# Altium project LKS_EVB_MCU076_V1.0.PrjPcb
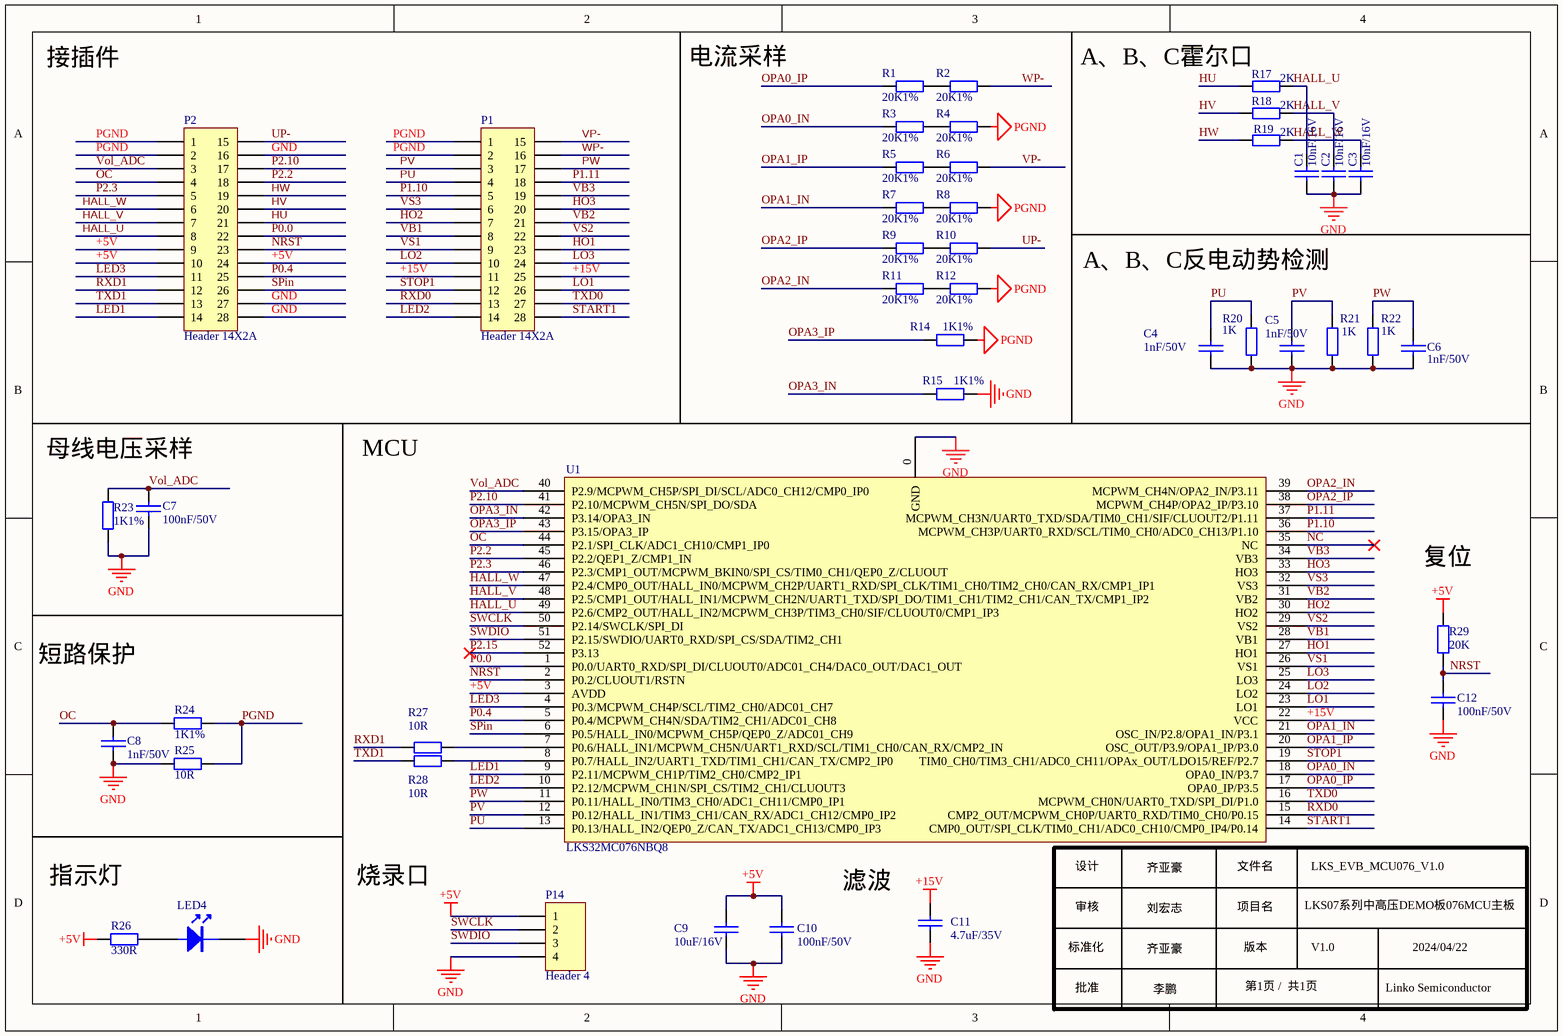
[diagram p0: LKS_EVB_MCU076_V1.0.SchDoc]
1 sheet, 44 parts. Net scope: global (net labels, ports and power ports of the same name join across sheets).
Board file: LKS_EVB_MCU076_V1.0.PcbDoc

## Sheet LKS_EVB_MCU076_V1.0.SchDoc
size A4; SheetNumber: 1; SheetTotal: 1

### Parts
C1  10nF/16V  [0603C]
C2  10nF/16V  [0603C]
C3  10nF/16V  [0603C]
C4  1nF/50V  [0603C]
C5  1nF/50V  [0603C]
C6  1nF/50V  [0603C]
C7  100nF/50V  [0603C]
C8  1nF/50V  [0603C]
C9  10uF/16V  [0603C]
C10  100nF/50V  [0603C]
C11  4.7uF/35V  [0603C]
C12  100nF/50V  [0603C]
LED4  LED  [LED 0603R]  (value not drawn)
P1  Header 14X2A  [HDR 2X14 底层]
P2  Header 14X2A  [HDR 2X14 底层]
P14  Header 4  [HDR 1X4]
R1  20K1%  [0603R]
R2  20K1%  [0603R]
R3  20K1%  [0603R]
R4  20K1%  [0603R]
R5  20K1%  [0603R]
R6  20K1%  [0603R]
R7  20K1%  [0603R]
R8  20K1%  [0603R]
R9  20K1%  [0603R]
R10  20K1%  [0603R]
R11  20K1%  [0603R]
R12  20K1%  [0603R]
R14  1K1%  [0603R]
R15  1K1%  [0603R]
R17  2K  [0603R]
R18  2K  [0603R]
R19  2K  [0603R]
R20  1K  [0603R]
R21  1K  [0603R]
R22  1K  [0603R]
R23  1K1%  [0603R]
R24  1K1%  [0603R]
R25  10R  [0603R]
R26  330R  [0603R]
R27  10R  [0603R]
R28  10R  [0603R]
R29  20K  [0603R]
U1  LKS32MC076NBQ8  [QFN52]

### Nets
+5V: C9.2 C10.2 P2.9 P2.10 P2.24 P14.1 R26.1 R29.1 U1.3(AVDD)
+15V: C11.2 P1.11 P1.25 U1.22(VCC)
GND: C1.2 C2.2 C3.2 C4.2 C5.2 C6.2 C7.1 C8.1 C9.1 C10.1 C11.1 C12.2 LED4.2(K) P2.16 P2.27 P2.28 P14.4 R15.1 R20.2 R21.2 R22.2 R23.1 R25.2 U1.0(GND)
PGND: P1.1 P1.2 P2.1 P2.2 R4.1 R8.1 R12.1 R14.1 R24.2 R25.1
HALL_U: C1.1 P2.8 R17.2 U1.49(P2.6/CMP2_OUT/HALL_IN2/MCPWM_CH3P/TIM3_CH0/SIF/CLUOUT0/CMP1_IP3)
HALL_V: C2.1 P2.7 R18.2 U1.48(P2.5/CMP1_OUT/HALL_IN1/MCPWM_CH2N/UART1_TXD/SPI_DO/TIM1_CH1/TIM2_CH1/CAN_TX/CMP1_IP2)
HALL_W: C3.1 P2.6 R19.2 U1.47(P2.4/CMP0_OUT/HALL_IN0/MCPWM_CH2P/UART1_RXD/SPI_CLK/TIM1_CH0/TIM2_CH0/CAN_RX/CMP1_IP1)
HO1: P1.23 U1.27(HO1)
HO2: P1.7 U1.30(HO2)
HO3: P1.20 U1.33(HO3)
HU: P2.21 R17.1
HV: P2.20 R18.1
HW: P2.19 R19.1
LED1: P2.14 U1.9(P2.11/MCPWM_CH1P/TIM2_CH0/CMP2_IP1)
LED2: P1.14 U1.10(P2.12/MCPWM_CH1N/SPI_CS/TIM2_CH1/CLUOUT3)
LED3: P2.11 U1.4(P0.3/MCPWM_CH4P/SCL/TIM2_CH0/ADC01_CH7)
LO1: P1.26 U1.23(LO1)
LO2: P1.10 U1.24(LO2)
LO3: P1.24 U1.25(LO3)
NC: U1.35(NC)
NRST: C12.1 P2.23 R29.2 U1.2(P0.2/CLUOUT1/RSTN)
OC: C8.2 P2.4 R24.1 U1.44(P2.1/SPI_CLK/ADC1_CH10/CMP1_IP0)
OPA0_IN: R3.2 U1.18(OPA0_IN/P3.7)
OPA0_IP: R1.2 U1.17(OPA0_IP/P3.5)
OPA1_IN: R7.2 U1.21(OSC_IN/P2.8/OPA1_IN/P3.1)
OPA1_IP: R5.2 U1.20(OSC_OUT/P3.9/OPA1_IP/P3.0)
OPA2_IN: R11.2 U1.39(MCPWM_CH4N/OPA2_IN/P3.11)
OPA2_IP: R9.2 U1.38(MCPWM_CH4P/OPA2_IP/P3.10)
OPA3_IN: R15.2 U1.42(P3.14/OPA3_IN)
OPA3_IP: R14.2 U1.43(P3.15/OPA3_IP)
P0.0: P2.22 U1.1(P0.0/UART0_RXD/SPI_DI/CLUOUT0/ADC01_CH4/DAC0_OUT/DAC1_OUT)
P0.4: P2.25 U1.5(P0.4/MCPWM_CH4N/SDA/TIM2_CH1/ADC01_CH8)
P1.10: P1.5 U1.36(MCPWM_CH3P/UART0_RXD/SCL/TIM0_CH0/ADC0_CH13/P1.10)
P1.11: P1.18 U1.37(MCPWM_CH3N/UART0_TXD/SDA/TIM0_CH1/SIF/CLUOUT2/P1.11)
P2.2: P2.18 U1.45(P2.2/QEP1_Z/CMP1_IN)
P2.3: P2.5 U1.46(P2.3/CMP1_OUT/MCPWM_BKIN0/SPI_CS/TIM0_CH1/QEP0_Z/CLUOUT)
P2.10: P2.17 U1.41(P2.10/MCPWM_CH5N/SPI_DO/SDA)
P2.15: U1.52(P3.13)
PU: C4.1 P1.4 R20.1 U1.13(P0.13/HALL_IN2/QEP0_Z/CAN_TX/ADC1_CH13/CMP0_IP3)
PV: C5.1 P1.3 R21.1 U1.12(P0.12/HALL_IN1/TIM3_CH1/CAN_RX/ADC1_CH12/CMP0_IP2)
PW: C6.1 P1.17 R22.1 U1.11(P0.11/HALL_IN0/TIM3_CH0/ADC1_CH11/CMP0_IP1)
RXD0: P1.13 U1.15(CMP2_OUT/MCPWM_CH0P/UART0_RXD/TIM0_CH0/P0.15)
RXD1: P2.12 R27.2
SPin: P2.26 U1.6(P0.5/HALL_IN0/MCPWM_CH5P/QEP0_Z/ADC01_CH9)
START1: P1.28 U1.14(CMP0_OUT/SPI_CLK/TIM0_CH1/ADC0_CH10/CMP0_IP4/P0.14)
STOP1: P1.12 U1.19(TIM0_CH0/TIM3_CH1/ADC0_CH11/OPAx_OUT/LDO15/REF/P2.7)
SWCLK: P14.2 U1.50(P2.14/SWCLK/SPI_DI)
SWDIO: P14.3 U1.51(P2.15/SWDIO/UART0_RXD/SPI_CS/SDA/TIM2_CH1)
TXD0: P1.27 U1.16(MCPWM_CH0N/UART0_TXD/SPI_DI/P1.0)
TXD1: P2.13 R28.1
UP-: P2.15 R10.1
VB1: P1.8 U1.28(VB1)
VB2: P1.21 U1.31(VB2)
VB3: P1.19 U1.34(VB3)
Vol_ADC: C7.2 P2.3 R23.2 U1.40(P2.9/MCPWM_CH5P/SPI_DI/SCL/ADC0_CH12/CMP0_IP0)
VP-: P1.15 R6.1
VS1: P1.9 U1.26(VS1)
VS2: P1.22 U1.29(VS2)
VS3: P1.6 U1.32(VS3)
WP-: P1.16 R2.1
NetLED4_1: LED4.1(A) R26.2
NetR1_1: R1.1 R2.2
NetR3_1: R3.1 R4.2
NetR5_1: R5.1 R6.2
NetR7_1: R7.1 R8.2
NetR9_1: R9.1 R10.2
NetR11_1: R11.1 R12.2
NetR27_1: R27.1 U1.7(P0.6/HALL_IN1/MCPWM_CH5N/UART1_RXD/SCL/TIM1_CH0/CAN_RX/CMP2_IN)
NetR28_2: R28.2 U1.8(P0.7/HALL_IN2/UART1_TXD/TIM1_CH1/CAN_TX/CMP2_IP0)

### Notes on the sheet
- 接插件
- 电流采样
- A、B、C霍尔口
- A、B、C反电动势检测
- 母线电压采样
- MCU
- 复位
- 短路保护
- 指示灯
- 烧录口
- (near U1) 滤波
- (near U1) 设计
- 审核
- (near U1) 齐亚豪
- 刘宏志
- (near U1) 文件名
- 项目名
- LKS07系列中高压DEMO板076MCU主板
- LKS_EVB_MCU076_V1.0
- 标准化
- 批准
- 齐亚豪
- 版本
- 第1页 /  共1页
- V1.0
- Linko Semiconductor
- 2024/04/22
- 李鹏

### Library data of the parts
C1-C6 = CAP: Capacitor
C7-C12 = C: Capacitor
LED4 = LED: LED_Light
P1 P2 = Header 14X2A: Header, 14-Pin, Dual row
P14 = Header 4: Header, 4-Pin
R1-R12 R14 R15 R17-R24 R29 = Res: Resistor; Value: K
R25 = Res: Resistor; Value: 10
R26 = Res: Resistor; Value: 330
R27 = Res2: Resistor
R28 = Res2: Resistor; Value: 100R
